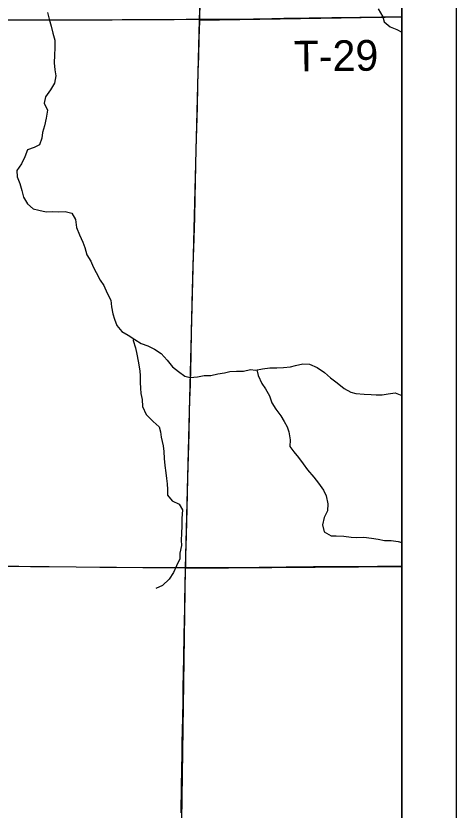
# Model space of a CAD drawing. Extents: x -11.1 to 34, y -3.9 to 22.
# Drawn here: x 8.187 to 9, y 15.825 to 17.295 of the extents above; entities that cross this region are included whole.
import ezdxf

# ---------------------------------------------------------------- set-up
doc = ezdxf.new("R2010")
doc.units = 0
for name, color, linetype in [('GM_X_Corporation', 7, 'Continuous'), ('GM_X_County_Road', 7, 'Continuous'), ('GM_X_Minor_River', 7, 'Continuous'), ('GM_X_State_Route', 7, 'Continuous'), ('GM_X_Township_Road', 7, 'Continuous'), ('GM_X_Township_Road_Text', 7, 'Continuous'), ('SH_Data', 7, 'Continuous')]:
    doc.layers.add(name, color=color, linetype=linetype)

msp = doc.modelspace()

# ---------------------------------------------------------------- linework, layer by layer
at = {"layer": 'GM_X_Corporation'}
for points in [[(8.9, 14.1), (8.9, 19.2515)], [(8.9, 15.2587), (8.9, 19.2515)]]:
    msp.add_lwpolyline(points, dxfattribs=at)
for points in [[(8.9, 17.2929), (8.9, 18.2314), (8.569, 18.2332), (8.5569, 18.2331), (8.525, 17.2867)], [(8.9, 16.2758), (8.9, 17.2929), (8.525, 17.2867), (8.4993, 16.2731)], [(8.9, 15.2568), (8.9, 16.2758), (8.4993, 16.2731), (8.4849, 15.2528)]]:
    msp.add_lwpolyline(points, close=True, dxfattribs=at)
at = {"layer": 'GM_X_County_Road'}
for points in [[(8.5258, 17.2886), (8.5364, 17.2885), (8.542, 17.2884), (8.5482, 17.2884), (8.5588, 17.2884), (8.5687, 17.2884), (8.5942, 17.2887), (8.6259, 17.2891), (8.6383, 17.2893), (8.6594, 17.2896), (8.6818, 17.2901), (8.6992, 17.2904), (8.7284, 17.2907), (8.7452, 17.291), (8.7706, 17.2913), (8.7949, 17.2915), (8.8222, 17.2919), (8.8334, 17.292), (8.8465, 17.2921), (8.8688, 17.2924), (8.8844, 17.2926), (8.9, 17.2927)], [(8.1503, 17.2873), (8.1975, 17.2872), (8.2505, 17.2871), (8.2615, 17.2871), (8.2932, 17.287), (8.3013, 17.287), (8.3243, 17.2873), (8.3491, 17.2875), (8.3647, 17.2875), (8.3833, 17.2877), (8.3901, 17.2878), (8.4069, 17.2877), (8.4137, 17.2877), (8.4311, 17.2877), (8.4429, 17.2878), (8.4504, 17.2879), (8.4572, 17.288), (8.4703, 17.2881), (8.479, 17.2881), (8.5013, 17.2882), (8.5258, 17.2886)]]:
    msp.add_lwpolyline(points, dxfattribs=at)
at = {"layer": 'GM_X_Minor_River'}
for points in [[(8.8563, 17.3073), (8.8648, 17.2927), (8.867, 17.2832), (8.8782, 17.2742), (8.8907, 17.2694), (8.9, 17.2643)], [(8.2452, 17.301), (8.248, 17.2884), (8.2516, 17.2754), (8.2548, 17.2624), (8.2584, 17.2494), (8.2585, 17.2353), (8.2582, 17.2216), (8.2576, 17.2079), (8.2589, 17.1949)], [(8.2589, 17.1949), (8.2606, 17.1835), (8.258, 17.1702), (8.2509, 17.1578), (8.2415, 17.1447), (8.2387, 17.1329), (8.2453, 17.1199), (8.2427, 17.1051), (8.2398, 17.0914), (8.2358, 17.0789), (8.2344, 17.0683), (8.2304, 17.0562), (8.2204, 17.0511), (8.2081, 17.0467), (8.2029, 17.0339), (8.1969, 17.0207), (8.1883, 17.0087), (8.1892, 16.9965), (8.1939, 16.9846), (8.1975, 16.9716), (8.2007, 16.9593), (8.2081, 16.9466), (8.2187, 16.9377), (8.2289, 16.9352), (8.2426, 16.9323), (8.2552, 16.9328), (8.2651, 16.9322), (8.2777, 16.9324), (8.2903, 16.9295), (8.2969, 16.9179), (8.2985, 16.9031), (8.304, 16.8893), (8.3103, 16.8762), (8.3139, 16.8659), (8.3179, 16.8528), (8.3249, 16.8405), (8.3293, 16.8305), (8.3352, 16.8198), (8.3426, 16.8056), (8.3489, 16.7959), (8.3551, 16.7813), (8.3621, 16.7686), (8.3634, 16.7561), (8.3655, 16.7435), (8.3691, 16.7335), (8.3731, 16.722), (8.3824, 16.7104), (8.3941, 16.7041), (8.4062, 16.6959), (8.4179, 16.6888), (8.4304, 16.684), (8.4425, 16.678), (8.455, 16.6698), (8.4662, 16.6578), (8.4759, 16.6454), (8.4868, 16.6365), (8.4988, 16.6279), (8.5087, 16.6258), (8.5221, 16.6271), (8.5344, 16.6295), (8.5466, 16.6296), (8.5596, 16.6321), (8.5722, 16.6345), (8.5818, 16.6366), (8.594, 16.6371), (8.607, 16.6376), (8.62, 16.6401), (8.6296, 16.6391), (8.6422, 16.6415), (8.6556, 16.6436), (8.669, 16.6437), (8.6812, 16.6442), (8.6938, 16.6451), (8.7034, 16.648), (8.7168, 16.6508), (8.729, 16.6502), (8.743, 16.6438), (8.7566, 16.6348), (8.7682, 16.6251), (8.7803, 16.6157), (8.7931, 16.6052), (8.8055, 16.5985), (8.815, 16.596), (8.8299, 16.5946), (8.8429, 16.5944), (8.8524, 16.5934), (8.8631, 16.5936), (8.8745, 16.5953), (8.8876, 16.597), (8.9, 16.5923)], [(8.4038, 16.6975), (8.4035, 16.694), (8.4074, 16.6802), (8.4099, 16.6688), (8.4127, 16.6558), (8.4158, 16.6382), (8.416, 16.6287), (8.4162, 16.6161), (8.4171, 16.6058), (8.4177, 16.5959), (8.4198, 16.5848), (8.4203, 16.5719), (8.4273, 16.5573), (8.4401, 16.5445), (8.4513, 16.5344), (8.4538, 16.5248), (8.4552, 16.5153), (8.4587, 16.4992), (8.46, 16.4885), (8.4606, 16.4759), (8.4619, 16.463), (8.4639, 16.4492), (8.4652, 16.4389), (8.4662, 16.429), (8.4668, 16.4183), (8.467, 16.4077), (8.4756, 16.3972), (8.4884, 16.3913), (8.4943, 16.3809), (8.4933, 16.3649), (8.4934, 16.3512), (8.4924, 16.3371), (8.4918, 16.325), (8.4928, 16.3151), (8.4898, 16.3006), (8.4896, 16.29), (8.4833, 16.2772), (8.4781, 16.2647), (8.4699, 16.2523), (8.4574, 16.2411), (8.4451, 16.2352)], [(8.6317, 16.6395), (8.6344, 16.6295), (8.6413, 16.6142), (8.6476, 16.6045), (8.655, 16.5914), (8.6594, 16.5788), (8.6668, 16.5672), (8.6761, 16.5545), (8.6824, 16.5441), (8.6876, 16.5345), (8.6908, 16.5249), (8.6932, 16.5104), (8.693, 16.4982), (8.7001, 16.4882), (8.7091, 16.4777), (8.7172, 16.4662), (8.7254, 16.455), (8.737, 16.441), (8.7456, 16.4302), (8.7549, 16.4171), (8.7597, 16.4067), (8.7628, 16.3922), (8.7622, 16.3789), (8.7563, 16.3664), (8.753, 16.3532), (8.7565, 16.3402), (8.769, 16.3327), (8.7785, 16.3325), (8.7923, 16.3319), (8.806, 16.3301), (8.8167, 16.3299), (8.8296, 16.33), (8.8437, 16.3283), (8.8559, 16.3265), (8.8677, 16.324), (8.8799, 16.3238), (8.8928, 16.3224), (8.9, 16.3206)]]:
    msp.add_lwpolyline(points, dxfattribs=at)
at = {"layer": 'GM_X_State_Route'}
for points in [[(8.5266, 17.3204), (8.5258, 17.2886), (8.5257, 17.285), (8.5247, 17.2533), (8.5238, 17.2191), (8.523, 17.1918), (8.5222, 17.1657), (8.5214, 17.1259), (8.5202, 17.0862), (8.5191, 17.0489), (8.5185, 17.0178), (8.5173, 16.9582), (8.5165, 16.9216), (8.5161, 16.9023), (8.5148, 16.8644), (8.5137, 16.8352), (8.5131, 16.8098), (8.5124, 16.788), (8.5116, 16.7644), (8.5111, 16.7327), (8.5107, 16.7135), (8.5098, 16.6644), (8.5092, 16.6427), (8.5084, 16.6128), (8.5077, 16.5843), (8.507, 16.5607), (8.5063, 16.5228), (8.5057, 16.501), (8.504, 16.4402), (8.5031, 16.4097), (8.5024, 16.3824), (8.5018, 16.3582), (8.5004, 16.3122), (8.5, 16.2973), (8.4999, 16.2739)], [(8.1602, 16.2766), (8.1919, 16.2764), (8.2136, 16.2761), (8.2484, 16.2757), (8.2981, 16.2754), (8.3416, 16.275), (8.3727, 16.2748), (8.4212, 16.2744), (8.456, 16.2741), (8.4999, 16.2739)], [(8.4999, 16.2739), (8.5388, 16.2741), (8.5544, 16.274), (8.5799, 16.2741), (8.6364, 16.2748), (8.6861, 16.2752), (8.711, 16.2754), (8.7364, 16.2757), (8.7638, 16.276), (8.8085, 16.276), (8.8545, 16.2765), (8.888, 16.2767), (8.9, 16.2768)]]:
    msp.add_lwpolyline(points, dxfattribs=at)
at = {"layer": 'GM_X_Township_Road'}
for points in [[(8.5258, 17.2886), (8.5364, 17.2885), (8.542, 17.2884), (8.5482, 17.2884), (8.5588, 17.2884), (8.5687, 17.2884), (8.5942, 17.2887), (8.6259, 17.2891), (8.6383, 17.2893), (8.6594, 17.2896), (8.6818, 17.2901), (8.6992, 17.2904), (8.7284, 17.2907), (8.7452, 17.291), (8.7706, 17.2913), (8.7949, 17.2915), (8.8222, 17.2919), (8.8334, 17.292), (8.8465, 17.2921), (8.8688, 17.2924), (8.8844, 17.2926), (8.9, 17.2927)], [(8.4919, 15.8204), (8.4926, 15.8695), (8.4938, 15.9304), (8.494, 15.9527), (8.4943, 15.9701), (8.4951, 16), (8.4955, 16.0242), (8.4959, 16.0515), (8.4969, 16.1068), (8.4974, 16.1497), (8.4985, 16.1982), (8.4989, 16.2143), (8.4993, 16.2398), (8.4999, 16.2739)]]:
    msp.add_lwpolyline(points, dxfattribs=at)
at = {"layer": 'SH_Data'}
for p, q in [((9, 21), (9, 14)), ((8.9, 20.9), (8.9, 14.1))]:
    msp.add_line(p, q, dxfattribs=at)

# ---------------------------------------------------------------- texts
at = {"layer": 'GM_X_Township_Road_Text'}
msp.add_text('T-29', height=0.05682, rotation=0.702, dxfattribs=at).set_placement((8.7004, 17.1914))

doc.saveas('drawing.dxf')
